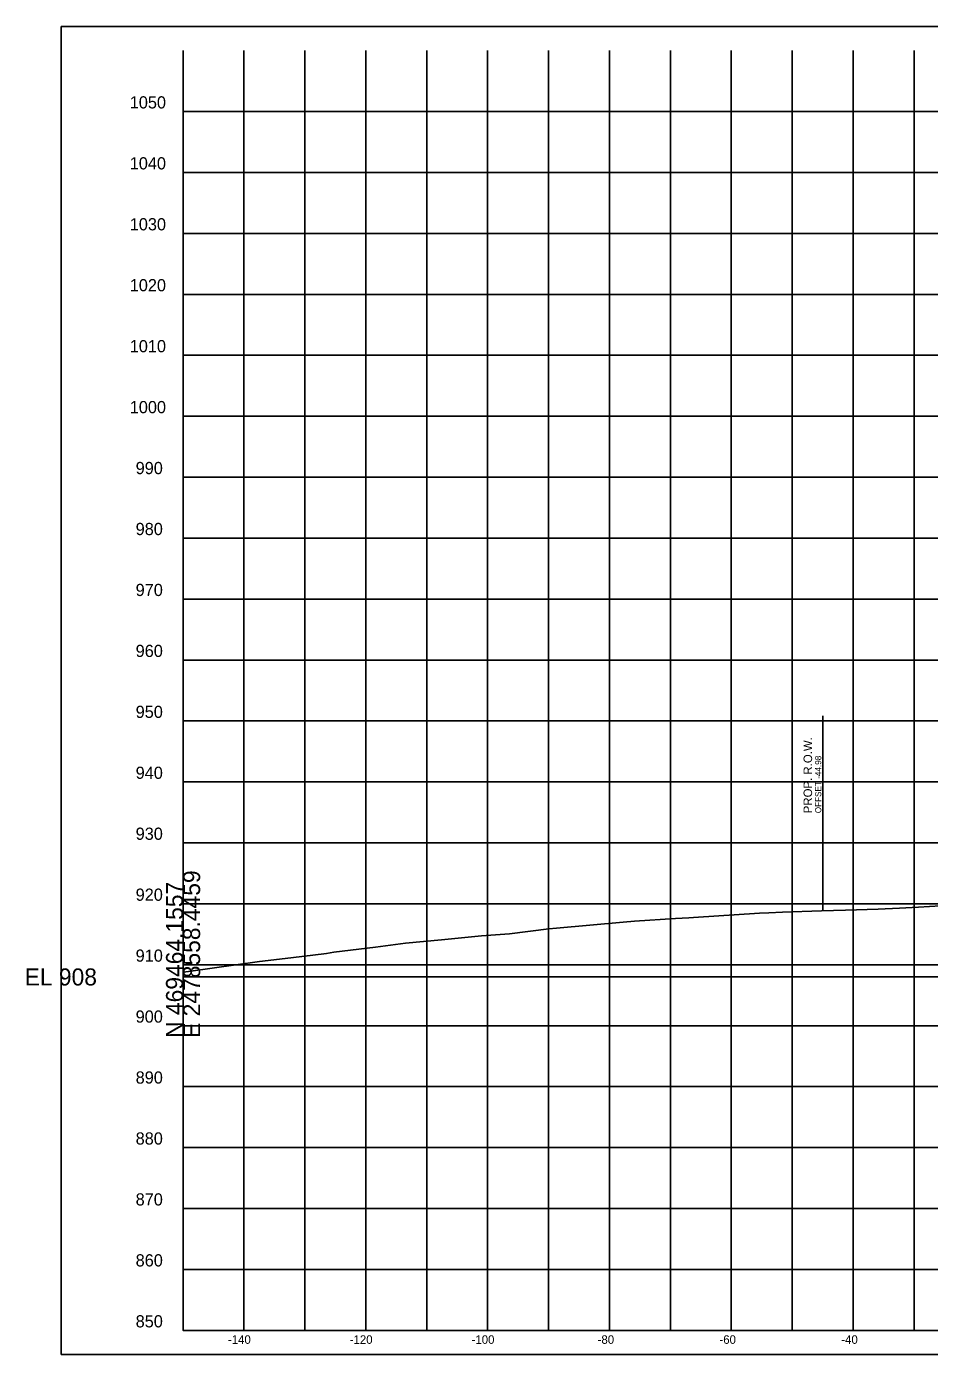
# Model space of a CAD drawing. Extents: x -26 to 2478923, y -10 to 469990.
# Drawn here: x -25.7 to 122.5, y 7938.1 to 8155.9 of the extents above; entities that cross this region are included whole.
import ezdxf

# ---------------------------------------------------------------- set-up
doc = ezdxf.new("R2010")
doc.units = 0
for name, color, linetype in [('DESIGN - ROW - Right-of-Way and Easement Labels', 7, 'Continuous'), ('DESIGN - ROW - Right-of-Way Linework', 7, 'Continuous'), ('DESIGN - SHEET - Corner Text', 7, 'Continuous'), ('DESIGN - SHEET - Light Grid', 7, 'Continuous'), ('DESIGN - SHEET - Linework', 7, 'Continuous'), ('DESIGN - SHEET - Plot Shape', 7, 'Continuous'), ('SURVEY - GROUND - Top of Ground', 7, 'Continuous')]:
    doc.layers.add(name, color=color, linetype=linetype)

msp = doc.modelspace()

# ---------------------------------------------------------------- linework, layer by layer
at = {"layer": 'DESIGN - ROW - Right-of-Way Linework'}
msp.add_line((105.02, 8010.86), (105.02, 8042.86), dxfattribs=at)
at = {"layer": 'DESIGN - SHEET - Light Grid'}
msp.add_line((0, 8000), (150, 8000), dxfattribs=at)
at = {"layer": 'DESIGN - SHEET - Linework'}
for p, q in [((10, 7942), (10, 8152)), ((10, 7942), (10, 8152)), ((10, 7942), (10, 8152)), ((10, 7942), (10, 8152)), ((20, 7942), (20, 8152)), ((20, 7942), (20, 8152)), ((20, 7942), (20, 8152)), ((20, 7942), (20, 8152)), ((30, 7942), (30, 8152)), ((30, 7942), (30, 8152)), ((30, 7942), (30, 8152)), ((30, 7942), (30, 8152)), ((40, 7942), (40, 8152)), ((40, 7942), (40, 8152)), ((40, 7942), (40, 8152)), ((40, 7942), (40, 8152)), ((50, 7942), (50, 8152)), ((50, 7942), (50, 8152)), ((50, 7942), (50, 8152)), ((50, 7942), (50, 8152)), ((60, 7942), (60, 8152)), ((60, 7942), (60, 8152)), ((60, 7942), (60, 8152)), ((60, 7942), (60, 8152)), ((70, 7942), (70, 8152)), ((70, 7942), (70, 8152)), ((70, 7942), (70, 8152)), ((70, 7942), (70, 8152)), ((80, 7942), (80, 8152)), ((80, 7942), (80, 8152)), ((80, 7942), (80, 8152)), ((80, 7942), (80, 8152)), ((90, 7942), (90, 8152)), ((90, 7942), (90, 8152)), ((90, 7942), (90, 8152)), ((90, 7942), (90, 8152)), ((100, 7942), (100, 8152)), ((100, 7942), (100, 8152)), ((100, 7942), (100, 8152)), ((100, 7942), (100, 8152)), ((110, 7942), (110, 8152)), ((110, 7942), (110, 8152)), ((110, 7942), (110, 8152)), ((110, 7942), (110, 8152)), ((120, 7942), (120, 8152)), ((120, 7942), (120, 8152)), ((120, 7942), (120, 8152)), ((120, 7942), (120, 8152)), ((0, 8142), (300, 8142)), ((0, 8142), (300, 8142)), ((0, 8142), (300, 8142)), ((0, 8142), (300, 8142)), ((0, 8132), (300, 8132)), ((0, 8132), (300, 8132)), ((0, 8132), (300, 8132)), ((0, 8132), (300, 8132)), ((0, 8122), (300, 8122)), ((0, 8122), (300, 8122)), ((0, 8122), (300, 8122)), ((0, 8122), (300, 8122)), ((0, 8112), (300, 8112)), ((0, 8112), (300, 8112)), ((0, 8112), (300, 8112)), ((0, 8112), (300, 8112)), ((0, 8102), (300, 8102)), ((0, 8102), (300, 8102)), ((0, 8102), (300, 8102)), ((0, 8102), (300, 8102)), ((0, 8092), (300, 8092)), ((0, 8092), (300, 8092)), ((0, 8092), (300, 8092)), ((0, 8092), (300, 8092)), ((0, 8082), (300, 8082)), ((0, 8082), (300, 8082)), ((0, 8082), (300, 8082)), ((0, 8082), (300, 8082)), ((0, 8072), (300, 8072)), ((0, 8072), (300, 8072)), ((0, 8072), (300, 8072)), ((0, 8072), (300, 8072)), ((0, 8062), (300, 8062)), ((0, 8062), (300, 8062)), ((0, 8062), (300, 8062)), ((0, 8062), (300, 8062)), ((0, 8052), (300, 8052)), ((0, 8052), (300, 8052)), ((0, 8052), (300, 8052)), ((0, 8052), (300, 8052)), ((0, 8042), (300, 8042)), ((0, 8042), (300, 8042)), ((0, 8042), (300, 8042)), ((0, 8042), (300, 8042)), ((0, 8032), (300, 8032)), ((0, 8032), (300, 8032)), ((0, 8032), (300, 8032)), ((0, 8032), (300, 8032)), ((0, 8022), (300, 8022)), ((0, 8022), (300, 8022)), ((0, 8022), (300, 8022)), ((0, 8022), (300, 8022)), ((0, 8012), (300, 8012)), ((0, 8012), (300, 8012)), ((0, 8012), (300, 8012)), ((0, 8012), (300, 8012)), ((0, 8002), (300, 8002)), ((0, 8002), (300, 8002)), ((0, 8002), (300, 8002)), ((0, 8002), (300, 8002)), ((0, 7992), (300, 7992)), ((0, 7992), (300, 7992)), ((0, 7992), (300, 7992)), ((0, 7992), (300, 7992)), ((0, 7982), (300, 7982)), ((0, 7982), (300, 7982)), ((0, 7982), (300, 7982)), ((0, 7982), (300, 7982)), ((0, 7972), (300, 7972)), ((0, 7972), (300, 7972)), ((0, 7972), (300, 7972)), ((0, 7972), (300, 7972)), ((0, 7962), (300, 7962)), ((0, 7962), (300, 7962)), ((0, 7962), (300, 7962)), ((0, 7962), (300, 7962)), ((0, 7952), (300, 7952)), ((0, 7952), (300, 7952)), ((0, 7952), (300, 7952)), ((0, 7952), (300, 7952))]:
    msp.add_line(p, q, dxfattribs=at)
msp.add_lwpolyline([(0, 8152), (0, 7942), (300, 7942), (300, 8152)], dxfattribs=at)
msp.add_lwpolyline([(0, 8152), (0, 7942), (300, 7942), (300, 8152)], dxfattribs=at)
msp.add_lwpolyline([(0, 8152), (0, 7942), (300, 7942), (300, 8152)], dxfattribs=at)
msp.add_lwpolyline([(0, 8152), (0, 7942), (300, 7942), (300, 8152)], dxfattribs=at)
at = {"layer": 'DESIGN - SHEET - Plot Shape'}
msp.add_lwpolyline([(-20, 8155.94), (320, 8155.94), (320, 7938.06), (-20, 7938.06)], close=True, dxfattribs=at)
msp.add_lwpolyline([(-20, 8155.94), (320, 8155.94), (320, 7938.06), (-20, 7938.06)], close=True, dxfattribs=at)
msp.add_lwpolyline([(-20, 8155.94), (320, 8155.94), (320, 7938.06), (-20, 7938.06)], close=True, dxfattribs=at)
msp.add_lwpolyline([(-20, 8155.94), (320, 8155.94), (320, 7938.06), (-20, 7938.06)], close=True, dxfattribs=at)
at = {"layer": 'SURVEY - GROUND - Top of Ground'}
msp.add_lwpolyline([(0, 8000.78), (0.89, 8000.87), (4.76, 8001.45), (12.53, 8002.54), (17.71, 8003.16), (23.56, 8003.87), (24.77, 8004.05), (31.58, 8004.9), (36.54, 8005.53), (42.44, 8006.11), (48.99, 8006.72), (53.57, 8007.09), (60.04, 8007.89), (61.3, 8008.01), (72.24, 8008.97), (74.12, 8009.15), (80.83, 8009.57), (83.06, 8009.72), (83.78, 8009.77), (94.62, 8010.44), (96.16, 8010.54), (98.39, 8010.65), (104.79, 8010.86), (108.73, 8010.93), (114.13, 8011.13), (117.64, 8011.29), (120.72, 8011.46), (129.77, 8011.99)], dxfattribs=at)

# ---------------------------------------------------------------- texts
at = {"layer": 'DESIGN - ROW - Right-of-Way and Easement Labels'}
for s, height, p in [('PROP. R.O.W.', 1.4, (103.27, 8026.86)), ('OFFSET -44.98', 1, (104.77, 8026.86))]:
    msp.add_text(s, height=height, rotation=90, dxfattribs=at).set_placement(p)
at = {"layer": 'DESIGN - SHEET - Corner Text'}
for s, height, p in [('1050', 2, (-8.75, 8142.5)), ('1050', 2, (-8.75, 8142.5)), ('1050', 2, (-8.75, 8142.5)), ('1050', 2, (-8.75, 8142.5)), ('1040', 2, (-8.75, 8132.5)), ('1040', 2, (-8.75, 8132.5)), ('1040', 2, (-8.75, 8132.5)), ('1040', 2, (-8.75, 8132.5)), ('1030', 2, (-8.75, 8122.5)), ('1030', 2, (-8.75, 8122.5)), ('1030', 2, (-8.75, 8122.5)), ('1030', 2, (-8.75, 8122.5)), ('1020', 2, (-8.75, 8112.5)), ('1020', 2, (-8.75, 8112.5)), ('1020', 2, (-8.75, 8112.5)), ('1020', 2, (-8.75, 8112.5)), ('1010', 2, (-8.75, 8102.5)), ('1010', 2, (-8.75, 8102.5)), ('1010', 2, (-8.75, 8102.5)), ('1010', 2, (-8.75, 8102.5)), ('1000', 2, (-8.75, 8092.5)), ('1000', 2, (-8.75, 8092.5)), ('1000', 2, (-8.75, 8092.5)), ('1000', 2, (-8.75, 8092.5)), ('990', 2, (-7.78, 8082.5)), ('990', 2, (-7.78, 8082.5)), ('990', 2, (-7.78, 8082.5)), ('990', 2, (-7.78, 8082.5)), ('980', 2, (-7.78, 8072.5)), ('980', 2, (-7.78, 8072.5)), ('980', 2, (-7.78, 8072.5)), ('980', 2, (-7.78, 8072.5)), ('970', 2, (-7.78, 8062.5)), ('970', 2, (-7.78, 8062.5)), ('970', 2, (-7.78, 8062.5)), ('970', 2, (-7.78, 8062.5)), ('960', 2, (-7.78, 8052.5)), ('960', 2, (-7.78, 8052.5)), ('960', 2, (-7.78, 8052.5)), ('960', 2, (-7.78, 8052.5)), ('950', 2, (-7.78, 8042.5)), ('950', 2, (-7.78, 8042.5)), ('950', 2, (-7.78, 8042.5)), ('950', 2, (-7.78, 8042.5)), ('940', 2, (-7.78, 8032.5)), ('940', 2, (-7.78, 8032.5)), ('940', 2, (-7.78, 8032.5)), ('940', 2, (-7.78, 8032.5)), ('930', 2, (-7.78, 8022.5)), ('930', 2, (-7.78, 8022.5)), ('930', 2, (-7.78, 8022.5)), ('930', 2, (-7.78, 8022.5)), ('920', 2, (-7.78, 8012.5)), ('920', 2, (-7.78, 8012.5)), ('920', 2, (-7.78, 8012.5)), ('920', 2, (-7.78, 8012.5)), ('910', 2, (-7.78, 8002.5)), ('910', 2, (-7.78, 8002.5)), ('910', 2, (-7.78, 8002.5)), ('910', 2, (-7.78, 8002.5)), ('900', 2, (-7.78, 7992.5)), ('900', 2, (-7.78, 7992.5)), ('900', 2, (-7.78, 7992.5)), ('900', 2, (-7.78, 7992.5)), ('890', 2, (-7.78, 7982.5)), ('890', 2, (-7.78, 7982.5)), ('890', 2, (-7.78, 7982.5)), ('890', 2, (-7.78, 7982.5)), ('880', 2, (-7.78, 7972.5)), ('880', 2, (-7.78, 7972.5)), ('880', 2, (-7.78, 7972.5)), ('880', 2, (-7.78, 7972.5)), ('870', 2, (-7.78, 7962.5)), ('870', 2, (-7.78, 7962.5)), ('870', 2, (-7.78, 7962.5)), ('870', 2, (-7.78, 7962.5)), ('860', 2, (-7.78, 7952.5)), ('860', 2, (-7.78, 7952.5)), ('860', 2, (-7.78, 7952.5)), ('860', 2, (-7.78, 7952.5)), ('850', 2, (-7.78, 7942.5)), ('850', 2, (-7.78, 7942.5)), ('850', 2, (-7.78, 7942.5)), ('850', 2, (-7.78, 7942.5)), ('-140', 1.4, (7.37, 7939.8)), ('-140', 1.4, (7.37, 7939.8)), ('-140', 1.4, (7.37, 7939.8)), ('-140', 1.4, (7.37, 7939.8)), ('-120', 1.4, (27.37, 7939.8)), ('-120', 1.4, (27.37, 7939.8)), ('-120', 1.4, (27.37, 7939.8)), ('-120', 1.4, (27.37, 7939.8)), ('-100', 1.4, (47.37, 7939.8)), ('-100', 1.4, (47.37, 7939.8)), ('-100', 1.4, (47.37, 7939.8)), ('-100', 1.4, (47.37, 7939.8)), ('-80', 1.4, (68.06, 7939.8)), ('-80', 1.4, (68.06, 7939.8)), ('-80', 1.4, (68.06, 7939.8)), ('-80', 1.4, (68.06, 7939.8)), ('-60', 1.4, (88.06, 7939.8)), ('-60', 1.4, (88.06, 7939.8)), ('-60', 1.4, (88.06, 7939.8)), ('-60', 1.4, (88.06, 7939.8)), ('-40', 1.4, (108.06, 7939.8)), ('-40', 1.4, (108.06, 7939.8)), ('-40', 1.4, (108.06, 7939.8)), ('-40', 1.4, (108.06, 7939.8))]:
    msp.add_text(s, height=height, dxfattribs=at).set_placement(p)
at = {"layer": 'DESIGN - SHEET - Light Grid'}
for s, p in [('E 2478558.4459', (2.8, 7990)), ('N 469464.1557', (0, 7990))]:
    msp.add_text(s, height=2.8, rotation=90, dxfattribs=at).set_placement(p)
msp.add_text('EL 908', height=2.8, dxfattribs=at).set_placement((-26, 7998.6))

doc.saveas('drawing.dxf')
